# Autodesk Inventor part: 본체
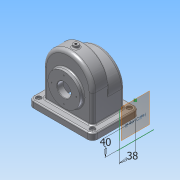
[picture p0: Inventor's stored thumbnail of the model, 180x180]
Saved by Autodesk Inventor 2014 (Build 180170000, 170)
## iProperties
Created: 2017-11
Part Number: 본체
Material: 알루미늄 6061
Document SubType Name: Modeling
Designer: sda
Density: 2.71 g/cm^3
Appearance: 알루미늄 - 평지
Mass: 1079.27 g
Surface Area: 1180.72 cm^2
Volume: 398.255 cm^3
Author: sda
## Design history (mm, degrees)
sketch "스케치1"
  geometry: L1 (-58, 0)-(58, 0); L2 (58, 0)-(58, -80); L3 (58, -80)-(-58, -80); L4 (-58, -80)-(-58, 0); C1 r 58 at (0, 0); 2 further points
  constraints: 8 end point, 2 coincident, 2 parallel, 1 centre point, 1 horizontal, 1 midpoint, 1 perpendicular
  dimensions: "d0" = 80 distance of L1.end L2.end; "d1" = 116 distance of L2.end L3.end; "d2" = 116 diameter of C1
extrude "돌출1" new body sketch "스케치1" distance "d3" = 38; taper "d4" = 0 deg
sketch "스케치2"
  geometry: L1 (-58, -80)-(58, -80) reference; L2 (58, -80)-(58, 0) reference; L3 (-58, -23)-(58, -23); L4 (58, -23)-(58, -80); L5 (58, -80)-(-58, -80); L6 (-58, -80)-(-58, -23); A1 r 58 centre (0, -23) between (58, -23) and (-10.724, -80); A2 r 58 centre (0, -23) between (10.724, -80) and (58, -23); A3 r 58 centre (0, -23) between (-10.724, -80) and (10.724, -80); 1 further point
  constraints: 8 end point, 6 point on circle, 3 centre point, 3 midpoint, 3 point on line, 2 parallel, 1 horizontal, 1 perpendicular
  dimensions: "d5" = 116 distance of L3.start L3.end; "d6" = 57 distance between parallel lines of L1 L3; "d8" = 58 radius of A2
extrude "돌출2" join sketch "스케치2" distance "d9" = 38; taper "d10" = 0 deg
sketch "스케치3"
  geometry: L1 (-58, -80)-(58, -80) reference; C1 r 37.5 at (0, -15); A1 r 58 centre (0, 0) between (58, 0) and (-58, 0) reference
  constraints: 1 centre point, 1 vertical alignment
  dimensions: "d11" = 75 diameter of C1; "d12" = 65 distance from line of C1.centre L1
extrude "돌출3" join sketch "스케치3" distance "d13" = 9; taper "d14" = 0 deg
sketch "스케치4"
  geometry: L1 (-58, -80)-(58, -80) reference; C1 r 31 at (0, -15); 1 further point
  constraints: 1 centre point, 1 vertical alignment
  dimensions: "d15" = 62 diameter of C1; "d16" = 65 distance from line of L1 C1.centre
extrude "돌출4" join sketch "스케치4" distance "d17" = 10; taper "d18" = 0 deg
node "작업 평면1"
node "작업 평면2"
sketch "스케치10"
  geometry: L1 (116, 0)-(116, -76) reference; L2 (0, 0)-(116, 0) reference; L3 (0, 0)-(0, -76) reference; L4 (116, -76)-(0, -76) reference; L5 (-17, 17)-(133, 17); L6 (133, 17)-(133, -93); L7 (133, -93)-(-17, -93); L8 (-17, -93)-(-17, 17); 3 further points
  constraints: 8 end point, 2 midpoint, 2 parallel, 1 horizontal, 1 horizontal alignment, 1 perpendicular, 1 vertical alignment
  dimensions: "d57" = 110 distance of L7.end L5.start; "d58" = 150 distance of L5.start L5.end
extrude "돌출8" join sketch "스케치10" distance "d59" = 15; taper "d60" = 0 deg
sketch "스케치14"
  geometry: L1 (58, 38)-(-58, 38) reference; L2 (75, -55)-(75, 55) reference; C1 r 6 at (0, 19); 1 further point
  constraints: 1 centre point
  dimensions: "d72" = 12 diameter of C1; "d73" = 19 distance from line of L1 C1.centre; "d74" = 75 distance from line of C1.centre L2
extrude "돌출11" join sketch "스케치14" distance "d75" = 64; taper "d76" = 0 deg
sketch "스케치15"
  geometry: L1 (75, -65)-(75, -80) reference; L2 (75, -80)-(-75, -80) reference; L3 (-75, -80)-(-75, -65) reference; L4 (-75, -65)-(-58, -65) reference; L5 (-58, -65)-(-58, 0) reference; L6 (-6, 57.689)-(-6, 64) reference; L7 (-6, 64)-(6, 64) reference; L8 (6, 64)-(6, 57.689) reference; L9 (58, 0)-(58, -65) reference; L10 (58, -65)-(75, -65) reference; L11 (53, 0)-(53, -80); L12 (-53, -80)-(-53, 0); A1 r 58 centre (0, 0) between (-6, 57.689) and (-58, 0) reference; A2 r 58 centre (0, 0) between (58, 0) and (6, 57.689) reference; A3 r 58 centre (0, 0) between (58, 0) and (-58, 0) reference; A4 r 53 centre (0, 0) between (53, 0) and (-53, 0); 1 further point
  constraints: 4 end point, 2 point on circle, 2 point on line, 1 centre point
  dimensions: "d77" = 5 radial gap between concentric circles of A2 A4; "d78" = 5 distance between parallel lines of L9 L11; "d79" = 5 distance between parallel lines of L5 L12
extrude "돌출12" cut sketch "스케치15" stored distance "d80" = 28; taper "d81" = 0 deg
sketch "스케치16"
  geometry: L1 (75, -65)-(75, -80) reference; L2 (75, -80)-(-75, -80) reference; L3 (-75, -80)-(-75, -65) reference; L4 (-75, -65)-(-58, -65) reference; L5 (-58, -65)-(-58, -23) reference; L6 (58, -23)-(58, -65) reference; L7 (58, -65)-(75, -65) reference; L8 (-53, -23)-(-53, -80); L9 (53, -80)-(53, -23); A1 r 58 centre (0, -23) between (58, -23) and (-58, -23) reference; A2 r 53 centre (0, -23) between (53, -23) and (-53, -23); 1 further point
  constraints: 4 end point, 2 point on circle, 2 point on line, 1 centre point, 1 other
  dimensions: "d82" = 5 radial gap between concentric circles of A1 A2; "d83" = 5 distance between parallel lines of L5 L8
extrude "돌출13" cut sketch "스케치16" distance "d84" = 28; taper "d86" = 0 deg; dims "d85" = 14, "d87" = 0
fillet "모깎기3" dims "d88" = 3
sketch "스케치17"
  geometry: C1 r 37.5 at (0, 0) reference; C2 r 16 at (0, 0); 1 further point
  constraints: 1 centre point, 1 coincident
  dimensions: "d89" = 32 diameter of C2
extrude "돌출14" cut sketch "스케치17" stored distance "d90" = 28; taper "d91" = 0 deg
sketch "스케치18" dims "d92" = 58
  geometry: C1 r 16 at (0, 0) reference; C2 r 37.5 at (0, 0) reference; 3 further points
  constraints: 2 vertical alignment, 1 coincident, 2 other
hole "구멍3" sketch "스케치18" at (0, 29) diameter "d93" = 2.459; stored, may be unused: countersink angle "d97" = 90 deg, drill point angle "d99" = 118 deg; dims "d94" = 6, "d95" = 4, "d96" = 2, "d98" = 8
sketch "스케치19" dims "d103" = 52
  geometry: C1 r 16 at (0, 0) reference; C2 r 31 at (0, 0) reference; 3 further points
  constraints: 2 vertical alignment, 1 coincident, 2 other
hole "구멍4" sketch "스케치19" at (0, 26) diameter "d104" = 2.459; stored, may be unused: countersink angle "d108" = 90 deg, drill point angle "d110" = 118 deg; dims "d105" = 6, "d106" = 4, "d107" = 2, "d109" = 8
sketch "스케치20"
  geometry: L1 (-17, -17)-(133, -17) reference; L2 (133, -17)-(133, 93) reference; C1 r 6 at (121, -5); 1 further point
  constraints: 1 centre point
  dimensions: "d114" = 12 diameter of C1; "d115" = 12 distance from line of L1 C1.centre; "d116" = 12 distance from line of L2 C1.centre
extrude "돌출15" cut sketch "스케치20" distance "d117" = 5; taper "d118" = 0 deg
sketch "스케치21"
  geometry: C1 r 6 at (0, 0) reference; C2 r 2.5 at (0, 0); 1 further point
  constraints: 1 centre point, 1 coincident
  dimensions: "d119" = 5 diameter of C2
extrude "돌출16" cut sketch "스케치21" stored distance "d120" = 5; taper "d121" = 0 deg
sketch "스케치22"
  geometry: C1 r 6 at (0, 0) reference; C2 r 2.5 at (0, 0); 1 further point
  constraints: 1 centre point, 1 coincident
  dimensions: "d128" = 5 diameter of C2
extrude "돌출17" cut sketch "스케치22" distance "d129" = 118.75; taper "d130" = 0 deg
feature "스레드1" dims "d131" = 10, "d132" = 0
chamfer "모따기1" distance "d133" = 1; stored, may be unused: second distance "d134" = 2, angle "d135" = 45 deg
fillet "모깎기4" dims "d136" = 12
fillet "모깎기5" dims "d137" = 8
fillet "모깎기6" dims "d138" = 3
node "작업 평면3"
sketch "스케치23"
  geometry: L1 (-13, -18)-(73, -18) reference; L2 (-8, 62)-(-8, 0) reference; 2 further points
  constraints: 1 other
  dimensions: "d140" = 40 distance from line of L1 point (30, 22); "d141" = 38 distance from line of point (30, 22) L2
node "솔리드1"
pattern_circular "원형 패턴3" dims angle "d101" = 360 deg
pattern_circular "원형 패턴4" dims angle "d112" = 360 deg
pattern_linear "직사각형 패턴1" dims "d124" = 86, "d127" = 126
node "절단 모서리 투영5"
node "절단 모서리 투영6"
other parameters: "d19" = 19, "d24" = -19, "d139" = 62.5
